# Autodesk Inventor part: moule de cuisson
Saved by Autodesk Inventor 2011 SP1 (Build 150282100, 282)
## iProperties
Created: 2010-12
Part Number: moule de cuisson
Document SubType Name: Modeling
Designer: eric
Density: 1 g/cm^3
Author: eric
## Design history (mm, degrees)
feature "Base1"
node "Solide1"
node "Corps solides"
node "Corps surfaciques"
